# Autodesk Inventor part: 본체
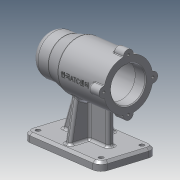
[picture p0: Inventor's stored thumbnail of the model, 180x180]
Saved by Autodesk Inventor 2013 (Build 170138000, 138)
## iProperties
Created: 2019-07
Part Number: 본체
Material: 알루미늄 6061
Document SubType Name: Modeling
Designer: user
Mass: 646.774 g
Surface Area: 654.083 cm^2
Volume: 238.662 cm^3
Density: 2.71 g/cm^3
Author: user
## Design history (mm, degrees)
sketch "스케치1"
  geometry: L1 (-56, 0)-(56, 0); L2 (-56, 0)-(-56, 25); L3 (-56, 25)-(-31, 25); L4 (-31, 25)-(-11, 30); L5 (-11, 30)-(56, 30); L6 (56, 30)-(56, 0); 2 further points
  constraints: 12 end point, 2 parallel, 2 perpendicular, 1 coincident, 1 horizontal, 1 midpoint
  dimensions: "d0" = 112 distance of L1.start L1.end; "d1" = 50 diameter of L3 L1; "d2" = 60 diameter of L5 L1; "d3" = 25 distance of L2.end L3.end; "d4" = 45 horizontal distance of L2.end L4.end
revolve "회전1" sketch "스케치1" stored, may be unused: angle "d5" = 90 deg
sketch "스케치2"
  geometry: L1 (-56, -25)-(-56, 25) reference; L2 (56, -30)-(56, 30) reference; L3 (-56, 0)-(56, 0); L4 (56, 21)-(41, 21); L5 (41, 21)-(41, 24); L6 (41, 24)-(-13, 24); L7 (-13, 24)-(-13, 21); L8 (-13, 21)-(-25, 21); L9 (-25, 21)-(-25, 17.5); L10 (-25, 17.5)-(-43, 17.5); L11 (-43, 17.5)-(-43, 16); L12 (-43, 16)-(-47, 16); L13 (-47, 16)-(-47, 10.5); L14 (-47, 10.5)-(-50, 10.5); L15 (-50, 10.5)-(-50, 0); 1 further point
  constraints: 26 end point, 9 parallel, 2 midpoint, 2 perpendicular, 2 point on line, 1 collinear
  dimensions: "d6" = 42 diameter of L4 L3; "d8" = 48 diameter of L6 L3; "d9" = 42 diameter of L8 L3; "d10" = 21 diameter of L14 L3; "d11" = 32 diameter of L12 L3; "d12" = 35 diameter of L10 L3; "d13" = 3 distance of L13.end L14.end; "d14" = 15 distance of L4.start L4.end; "d15" = 54 distance of L5.end L6.end; "d16" = 12 distance of L7.end L8.end; "d17" = 18 distance of L9.end L10.end; "d18" = 4 distance of L11.end L12.end
revolve "회전2" sketch "스케치2" stored, may be unused: angle "d19" = 90 deg
fillet "모깎기1" dims "d20" = 10
fillet "모깎기2" dims "d21" = 3
fillet "모깎기3" dims "d22" = 3
fillet "모깎기4" dims "d23" = 0.3
sketch "스케치3"
  geometry: L1 (0, 0)-(0, 30); C1 r 30 at (0, 0) reference; C2 r 6 at (0, 30)
  constraints: 2 end point, 1 centre point, 1 coincident, 1 vertical
  dimensions: "d24" = 30 distance of L1.start L1.end; "d25" = 12 diameter of C2
extrude "돌출1" join sketch "스케치3" distance "d26" = 16; taper "d27" = 0 deg
sketch "스케치4"
  geometry: A1 r 6 centre (0, 0) between (5.97, -0.6) and (-5.97, -0.6) reference; 1 further point
  constraints: 1 coincident
hole "구멍1" sketch "스케치4" at (0, 0) diameter "d28" = 3.242; stored, may be unused: countersink angle "d32" = 90 deg, drill point angle "d34" = 118 deg; dims "d29" = 8, "d30" = 4, "d31" = 2, "d33" = 11
fillet "모깎기5" dims "d38" = 3
fillet "모깎기6" dims "d39" = 1
node "작업 평면1"
sketch "스케치5"
  geometry: L1 (-56, -6.771)-(-56, -29.226) reference; L2 (-56, -5.998)-(-56, 5.998) reference; L3 (-56, 29.226)-(-56, 6.771) reference; L4 (56, -35)-(-56, -35); L5 (-56, -35)-(-56, 35); L6 (-56, 35)-(56, 35); L7 (56, 35)-(56, -35); L8 (56, -35)-(-56, 35); L9 (-56, -35)-(56, 35); 3 further points
  constraints: 12 end point, 4 midpoint, 2 parallel, 1 horizontal, 1 perpendicular
  dimensions: "d41" = 112 distance of L5.end L6.end; "d42" = 70 distance of L4.end L5.end
extrude "돌출2" join sketch "스케치5" distance "d43" = 10; taper "d44" = 0 deg
fillet "모깎기7" dims "d45" = 10
sketch "스케치6"
  geometry: L1 (56, -25)-(56, 25) reference; L2 (-36, 4)-(31, 4); L3 (31, 4)-(31, -4); L4 (31, -4)-(-36, -4); L5 (-36, -4)-(-36, 4); 1 further point
  constraints: 8 end point, 2 parallel, 1 horizontal, 1 perpendicular
  dimensions: "d46" = 67 distance of L3.end L4.end; "d47" = 8 distance of L2.end L3.end; "d48" = 25 distance between parallel lines of L1 L3; "d49" = 4 distance from line of point (0, 0) L2
extrude "돌출3" join sketch "스케치6" stored distance "d50" = 10; taper "d51" = 0 deg
feature "면 기울기1" dims angle "d52" = 20 deg
sketch "스케치7"
  geometry: L1 (-70, 4)-(-27.341, 4) reference; L2 (-70, -25)-(-70, 25) reference; L3 (-70, 35)-(-70, 25) reference; L4 (-70, 28)-(-22.666, 19.654); L5 (-80, 35)-(-70, 35) reference; A1 r 30 centre (0, 0) between (-29.732, -4) and (-29.732, 4) reference; 1 further point
  constraints: 2 end point, 1 point on circle, 1 point on line
  dimensions: "d53" = 7 distance from line of L5 L4.start; "d54" = 100 deg angle of L3 L4
feature "리브1" sketch "스케치7" dims "d55" = 1, "d56" = 8, "d57" = 0, "d58" = 0, "d59" = 1, "d60" = 1
sketch "스케치8"
  geometry: A1 r 10 centre (46, -25) between (46, -35) and (56, -25) reference; A2 r 10 centre (46, 25) between (56, 25) and (46, 35) reference; A3 r 10 centre (-46, 25) between (-46, 35) and (-56, 25) reference; A4 r 10 centre (-46, -25) between (-56, -25) and (-46, -35) reference; 5 further points
  constraints: 4 coincident
hole "구멍2" sketch "스케치8" at (-46, 25), (-46, -25), (46, -25), (46, 25) diameter "d61" = 6; stored, may be unused: countersink angle "d65" = 90 deg, drill point angle "d67" = 118 deg; dims "d62" = 8, "d63" = 4, "d64" = 2, "d66" = 11
chamfer "모따기1" distance "d68" = 3; stored, may be unused: second distance "d69" = 2, angle "d70" = 45 deg
chamfer "모따기2" distance "d71" = 1; stored, may be unused: second distance "d72" = 2, angle "d73" = 45 deg
fillet "모깎기8" dims "d74" = 3
fillet "모깎기9" dims "d75" = 3
node "작업 평면2"
sketch "스케치9"
  geometry: L1 (56, 6.771)-(56, 29.226) reference; 2 further points
  constraints: 1 horizontal alignment, 1 other
  dimensions: "d77" = 42 distance from line of L1 point (14, 0)
feature "엠보싱1" sketch "스케치9" dims "d6" = 42, "d8" = 48, "d9" = 42, "d10" = 21, "d11" = 32, "d12" = 35, "d13" = 3, "d14" = 15, "d15" = 54, "d16" = 12, "d17" = 18, "d18" = 4, "d78" = 0.5, "d79" = 0
node "솔리드1"
pattern_circular "원형 패턴1" dims angle "d36" = 360 deg
mirror "대칭1"
other parameters: "d76" = 68
